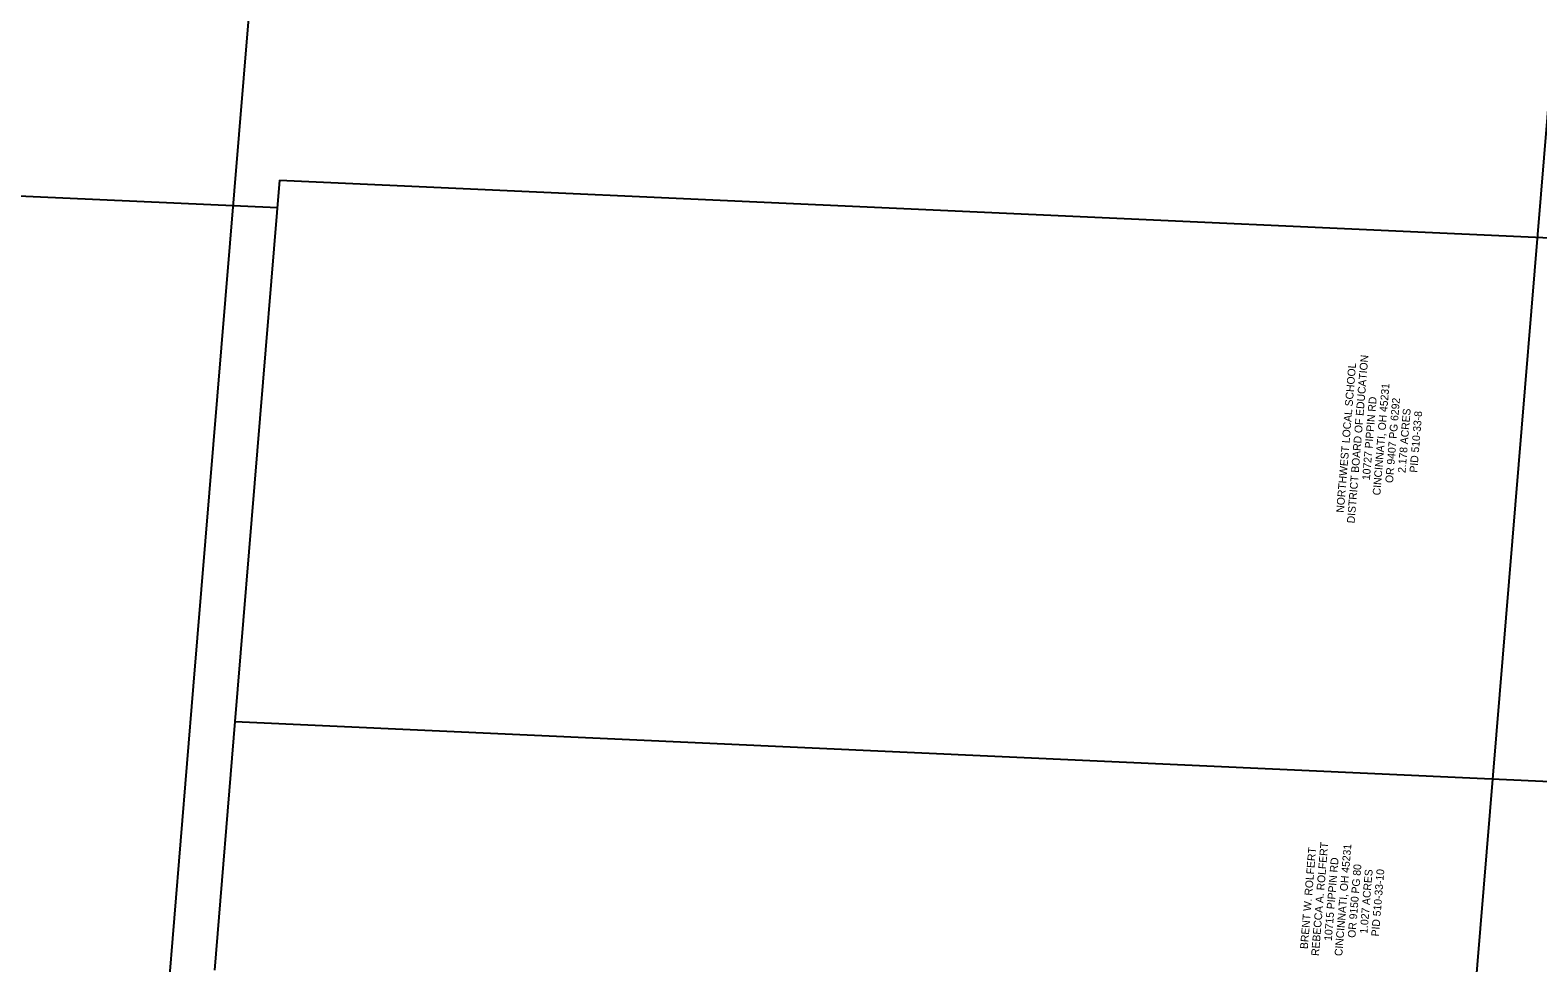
# Model space of a CAD drawing. Extents: x 1379776 to 1382941, y 467490 to 471592.
# Drawn here: x 1381007 to 1381551, y 469498 to 469835 of the extents above; entities that cross this region are included whole.
import ezdxf

# ---------------------------------------------------------------- set-up
doc = ezdxf.new("R2010")
doc.units = 0
for name, color, linetype in [('PV_P_Drive', 7, 'Continuous'), ('PV_X_Driveway', 7, 'Continuous'), ('RC_X_Text', 7, 'Continuous'), ('SH_Named_Boundary', 7, 'Continuous')]:
    doc.layers.add(name, color=color, linetype=linetype)

msp = doc.modelspace()

# ---------------------------------------------------------------- linework, layer by layer
at = {"layer": 'PV_P_Drive'}
for p, q in [((1380349.86, 469804.55), (1381096.09, 469770.57)), ((1381096.92, 469780.54), (1381080.78, 469585.21)), ((1381096.92, 469780.54), (1381580.75, 469758.51)), ((1381080.78, 469585.21), (1381073.36, 469495.51)), ((1381080.78, 469585.21), (1381564.61, 469563.17))]:
    msp.add_line(p, q, dxfattribs=at)
at = {"layer": 'PV_X_Driveway'}
msp.add_lwpolyline([(1381481.91, 468926.74), (1381589.94, 470234.06), (1380557.84, 470275.29)], dxfattribs=at)
at = {"layer": 'SH_Named_Boundary'}
msp.add_lwpolyline([(1381019.66, 469039.84), (1381836.87, 468972.31), (1381848.4, 469111.83), (1381859.93, 469251.36), (1381871.46, 469390.88), (1381882.99, 469530.4), (1381894.52, 469669.93), (1381906.05, 469809.45), (1381917.58, 469948.98), (1381929.11, 470088.5), (1381940.64, 470228.03), (1381952.16, 470367.55), (1381134.95, 470435.08), (1381123.42, 470295.56), (1381111.89, 470156.03), (1381100.36, 470016.51), (1381088.83, 469876.98), (1381077.3, 469737.46), (1381065.77, 469597.93), (1381054.24, 469458.41), (1381042.71, 469318.88), (1381031.19, 469179.36)], close=True, dxfattribs=at)

# ---------------------------------------------------------------- texts
at = {"layer": 'RC_X_Text'}
for s, p in [('DISTRICT BOARD OF EDUCATION', (1381484.72, 469656.6)), ('NORTHWEST LOCAL SCHOOL', (1381480.83, 469660.43)), ('CINCINNATI, OH 45231', (1381493.99, 469666.7)), ('10727 PIPPIN RD', (1381490.23, 469672.19)), ('OR 9407 PG 6292', (1381498.57, 469671.14)), ('2.178 ACRES', (1381503.08, 469674.77)), ('PID 510-33-8', (1381507.31, 469674.89)), ('REBECCA A. ROLFERT', (1381471.83, 469500.53)), ('BRENT W. ROLFERT', (1381467.82, 469503.01)), ('10715 PIPPIN RD', (1381476.49, 469505.96)), ('CINCINNATI, OH 45231', (1381480.25, 469500.47)), ('OR 9150 PG 80', (1381485.01, 469507.07)), ('1.027 ACRES', (1381489.35, 469508.54)), ('PID 510-33-10', (1381493.48, 469507.57))]:
    msp.add_text(s, height=2.8, rotation=85.2762, dxfattribs=at).set_placement(p)

doc.saveas('drawing.dxf')
